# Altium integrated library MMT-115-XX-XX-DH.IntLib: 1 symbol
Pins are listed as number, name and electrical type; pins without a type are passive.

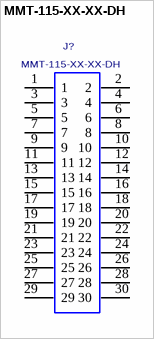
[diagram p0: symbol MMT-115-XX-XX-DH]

## MMT-115-XX-XX-DH
designator J?
2MM HORIZONTAL TERMINAL SURFACE MOUNT STRIP ASM, 30 PINS.; MANUFACTURER: SAMTEC
footprint MMT-115-XX-XX-DH
pins: 1, 2, 3, 4, 5, 6, 7, 8, 9, 10, 11, 12, 13, 14, 15, 16, 17, 18, 19, 20, 21, 22, 23, 24, 25, 26, 27, 28, 29, 30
